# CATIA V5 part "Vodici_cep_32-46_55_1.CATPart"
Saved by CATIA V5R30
Part number: Vodici_cep_32-46_55_1
Definition: E 1000_32-46_55_1
Nomenclature: E 1000_32-46_55_1
Source: Unknown
Description: PART--DESC
Bounding box of the stored display mesh (mm): x -210.3 to -163.7, y 113.7 to 160.3, z -101 to 9
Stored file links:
  E:\Bakalarka\Model\Forma_v7\Vodici_cep_32-46_55_1.CATPart
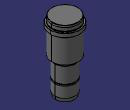
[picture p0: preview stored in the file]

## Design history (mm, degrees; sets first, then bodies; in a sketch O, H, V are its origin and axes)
Body1 "MANIFOLD_SOLID_BREP #3954" (main body)
  Solid1: solid without history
